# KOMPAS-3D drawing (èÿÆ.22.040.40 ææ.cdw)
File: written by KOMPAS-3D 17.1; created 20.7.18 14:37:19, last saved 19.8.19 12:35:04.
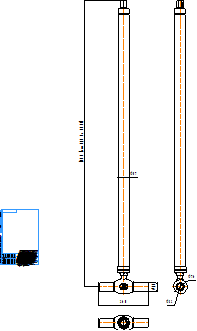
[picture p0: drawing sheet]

Sheet 1: A4, portrait

Title block, sheet 1: name: КШТ.22.040.40 С/С; sheets: 1; sheet format: A4; stored path: C:\Users\kka\KOMPAS_Work\Модели кранов для исследований\DN40\С удлинением\КШТ.22.040.40 СС.cdw

Views: Вид 1, Спереди
Referenced files in C:\Users\kka\KOMPAS_Work\Модели кранов для исследований\DN32\С удлинением\: КШГ.32.032.40 СС.a3d
Referenced files in C:\Users\kka\KOMPAS_Work\Модели кранов для исследований\DN40\С удлинением\: КШТ.22.040.40 СС.a3d
Referenced files in C:\Users\kka\KOMPAS_Work\Модели кранов для исследований\DN40\: АПТА.0203-1181.04.02 _ Корпус крана Ду40 (Труба по ГОСТ).m3d, АПТА.0203-2613.11.01 _ Шток Ду40-50.m3d, АПТА.0203-2613.12.01 _ Корпус штока Ду40-50.m3d, АПТА.0203-2613.11.02 _ Шар Ду40.m3d, АПТА.0203-1181.00.00 _ Кран шаровой сварной Ду40 (труба по ГОСТ).a3d!АПТА.0203-1181.00.00!Деталь (локальная).m3d, АПТА.0203-1181.03.01 _ Патрубок сварной точенный Ду40 (труба по ГОСТ).m3d, АПТА.0203-2613.02.02 _ Кольцо горловое Ду40.m3d, АПТА.0203-2613.02.04 _ Кольцо опорное Ду40.m3d, АПТА.0203-2613.02.05 _ Уплотнение седловое Ду40.m3d, АПТА.0203-2613.02.03 _ Пружина тарельчатая Ду40.m3d, АПТА.0203-1181.00.00 _ Кран шаровой сварной Ду40 (труба по ГОСТ).a3d!АПТА.0203-1181.00.00!Деталь (локальная) 1.m3d, АПТА.0203-1181.00.00 _ Кран шаровой сварной Ду40 (труба по ГОСТ).a3d
Referenced files in C:\Users\kka\KOMPAS_Work\Модели кранов для исследований\DN50\: АПТА.0203-2613.11.06 _ Кольцо прокладочное Ду40-50.m3d, Кольцо EPDM 14.3x2.4.m3d, Кольцо Viton 14.3x2.4.m3d, АПТА.0203-2613.11.04 _ Подкладка для кольца Ду40-50.m3d, АПТА.0203-2613.11.03 _ Шайба фрикционная Ду40-50.m3d, АПТА.0203-2613.11.05 _ Шайба штока Ду40-50.m3d
Referenced files in C:\Program Files\ASCON\KOMPAS-3D v17\Libs\PartLib\DATA\VAULT\methods\kompas\3d\: PLib_Parallel_Pin_ISO_1100.m3d, PLib_Blind_Nut_type1_900.m3d, PLib_Check_spring_rings_GOST_13942_911.m3d, PLib_Pin_3128_712.m3d, PLib_Bolt_1_900.m3d, PLib_Washer_2_712.m3d
Referenced files in C:\Users\kka\KOMPAS_Work\КШ удлиненные ПП МОСФЛОУЛАЙН ф. ADL\DN32ПП\: АПТА.0203-2613.03.02 _ Ухватка Ду40-50.m3d, АПТА.0203-2613.03.01 _ Рукоятка Ду40-50.m3d, АПТА.0203-2613.03.00 _ Ручка Ду40-50.a3d
Referenced files in C:\Users\kka\KOMPAS_Work\Удлинения БИВАЛ ф. ADL\Небюджет\Специальные ISO фланцы\: Фланец Ду40-50.m3d
Referenced files in C:\Users\kka\KOMPAS_Work\Удлинения БИВАЛ ф. ADL\Небюджет\Удлинения_2010\УШДн40-50\: УШ.261.00.03 _ Фланец нижний Ду20-50.m3d, УШ.251.00.07 _ Прокладка Ду20-50.m3d, УШ.261.01.01 _ Головка штока Ду20-80.m3d, УШ.266.01.02 _ Адаптер Ду40-50.m3d, УШ.266.00.00 _ Удлинение штока Ду40-50.a3d!УШ.266.00.00!Деталь (локальная).m3d, УШ.261.00.05 _ Крышка корпуса Ду20-80.m3d, УШ.261.00.06 _ Кольцо запорное Ду20-150.m3d, УШ.266.00.00 _ Удлинение штока Ду40-50.a3d!УШ.266.00.00!Деталь (локальная) 1.m3d, УШ.266.00.00 _ Удлинение штока Ду40-50.a3d
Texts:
  kka
  adl
  (от 245 до 5000)
  Рама для чертежей
  Лит-Масса-Масштаб
  Материал-Предприятие
  Масштаб
  Изм.
  Лист
  № докум.
  Подп.
  Дата
  Лит.
  Разраб.
  Пров.
  Т.контр.
  Листов
  Внимание! Данный продукт является объектом авторского права ООО «Торговый Дом АДЛ».
  Запрещается изменение, копирование, распространение
  (в том числе путем копирования на другие сайты и ресурсы в Интернете)
  или любое иное использование информации и объектов без предварительного
  согласия правообладателя (ООО «Торговый Дом АДЛ»).
  Н.контр.
  Утв.
  ООО "Торговый дом АДЛ"
  Изменение
  Номер документа
  Подпись
  Обозначение документа
  Наименование изделия
  Масса изделия по ГОСТ 2.109-73
  Порядковый номер листа
  Общее количество листов в документе
  Характер работы, выполненной лицом, подписавшим документ
  Наименование или индекс предприятия, выпускающего документ
  Инв. № подл.
  Подп. и дата
  Взам. инв. №
  Инв. № дубл.
  Инвентарный номер подлинника по ГОСТ 2.501-68
  Подпись принявшего подлинник в отдел технической документации
  Инвентарный номер подлинника, взамен которого выпущен данный подлинник
  Инвентарный номер дубликата по ГОСТ 2.502-68
  Подпись принявшего дубликат в отдел технической документации
  Справ. №
  Перв. примен.
  Обозначение документа, взамен или на основании которого выпущен данный документ
  Обозначение документа, в котором впервые записан данный документ
  Подпись лица, копировавшего чертеж
  Обозначение формата листа
  !Рама для чертежа
  Корпус крана Ду40 (Труба по ГОСТ)
  АПТА.0203-1181.04.02
  Шток Ду40-50
  АПТА.0203-2613.11.01
  Корпус штока Ду40-50
  АПТА.0203-2613.12.01
  Кольцо прокладочное Ду40-50
  АПТА.0203-2613.11.06
  Кольцо EPDM 14.3x2.4
  Кольцо Viton 14.3x2.4
  Подкладка для кольца Ду40-50
  АПТА.0203-2613.11.04
  Шайба фрикционная Ду40-50
  АПТА.0203-2613.11.03
  Шайба штока Ду40-50
  АПТА.0203-2613.11.05
  Parallel pin ISO 2338 - 4 h8 x 28 - A1
  Шар Ду40
  АПТА.0203-2613.11.02
  Деталь (локальная)
  Патрубок сварной точенный Ду40 (труба по ГОСТ)
  АПТА.0203-1181.03.01
  Кольцо горловое Ду40
  АПТА.0203-2613.02.02
  Кольцо опорное Ду40
  АПТА.0203-2613.02.04
  Уплотнение седловое Ду40
  АПТА.0203-2613.02.05
  Пружина тарельчатая Ду40
  АПТА.0203-2613.02.03
  Шов
  Ухватка Ду40-50
  АПТА.0203-2613.03.02
  Рукоятка Ду40-50
  АПТА.0203-2613.03.01
  Ручка Ду40-50
  АПТА.0203-2613.03.00
  Гайка М14-6H (S21) ГОСТ 11860-85
  Фланец для присоединения  приводов Ду 40-50
  ФС.4050.00.01
  Кран шаровой сварной Ду40 (труба по ГОСТ)
  АПТА.0203-1181.00.00
  Фланец нижний Ду20-50
  УШ.261.00.03
  Прокладка Ду20-50
  УШ.251.00.07
  Головка штока Ду20-80
  УШ.261.01.01
  Адаптер Ду40-50
  УШ.266.01.02
  Удлинитель
  Крышка корпуса Ду20-80
  УШ.261.00.05
  Кольцо A36.65 ГОСТ 13942-86
  Кольцо запорное Ду20-150
  УШ.261.00.06
  Корпус
  Штифт 2.8x16 ГОСТ 3128-70
  Штифт 2.10x45 ГОСТ 3128-70
  Болт М6-6gx25.68.019 ГОСТ 7805-70
  Шайба 6 65Г 019 ГОСТ 6402-70
  Удлинение штока Ду40-50
  УШ.266.00.00
Dimensions and other numbers on the sheet: 260; 1500; 48; 57; 1:1; 1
